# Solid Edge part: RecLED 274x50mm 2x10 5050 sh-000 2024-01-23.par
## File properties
Author: jaroslaw.przewlocki
Template: iso metric part.par
Last saved by: jaroslaw.przewlocki
Revision: 2
Application: Solid Edge
Gęstość: 0,000 kg/m^3
Dokładność: 0,990
Username: jaroslaw.przewlocki
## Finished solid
Body 1: solid body, 1056 faces, 2675 edges, 1702 vertices.
  Faces by surface: plane 523, cylinder 269, torus 104, cone 88, spline 51, sphere 20, swept 1
  Edges by curve: line 1410, curve on surface 677, circle 296, spline 160, ellipse 132
Bounding box of the edges (mm; curved faces can reach further): 49.500 x 4.950 x 273.800, from (-24.75, -3.45, -111.5) to (24.75, 1.5, 162.3).
Cylindrical faces by radius (mm): R0.199 x2, R0.2 x78, R0.2002 x4, R0.2169 x6, R0.25 x24, R0.3 x4, R0.3373 x6, R0.4 x16, R0.4006 x4, R0.4008 x4, R0.525 x4, R0.6 x24, R1 x14, R1.05 x20, R1.0894 x4, R1.0991 x8, R1.1 x28, R1.5342 x3, R1.5343 x1, R1.75 x5, R3.7549 x1, R5.3685 x1, R5.3987 x1, R5.4728 x1, R5.8982 x1, R7.5931 x1, R7.8648 x1, R8.5931 x1, R10.3711 x1, R11.964 x1
Conical faces (half-angle, radius in mm at the cone's reference point): 0.3913 deg R1.0968 x4, 0.447 deg R1.0952 x4, 0.464 deg R1.0955 x4, 0.5 deg R0.5056 x8, 0.5 deg R1.0082 x8, 1 deg R0.5511 x4, 10 deg R0.2132 x4, 10 deg R0.4132 x4, 15.6748 deg R1.1041 x2, 15.6751 deg R1.1041 x2, 15.7937 deg R1.1267 x2, 15.7938 deg R1.1267 x2, 18.4844 deg R1.0657 x8, 18.9316 deg R0.5099 x4, 19.4337 deg R0.5111 x4, 27.363 deg R0.6214 x4, 40.1968 deg R0.519 x2, 40.228 deg R0.5176 x2, 42.9179 deg R0.4919 x2, 42.9331 deg R0.4916 x2, 45 deg R0.575 x4, 45 deg R0.625 x8
Toroidal faces (ring radius, tube radius in mm): R0.0958 r0.3997 x8, R0.1 r0.2 x2, R0.1075 r0.4 x4, R0.1101 r0.4001 x4, R0.1216 r0.4 x4, R0.1234 r0.4 x4, R0.1634 r0.2287 x2, R0.1641 r0.2287 x2, R0.3286 r0.2001 x2, R0.3702 r0.4 x4, R0.3818 r0.2 x4, R0.4163 r0.3984 x4, R0.4824 r0.2001 x2, R0.4952 r0.2 x2, R0.6008 r0.3968 x4, R0.6009 r0.3969 x4, R0.6227 r0.2 x2, R0.6235 r0.2 x2, R0.8 r0.2 x8, R0.8522 r0.3 x4, R0.9002 r0.2 x2, R0.9018 r0.2 x2, R0.9181 r0.2227 x4, R0.9197 r0.223 x2, R0.9199 r0.223 x2, R0.9663 r0.2263 x2, R0.9665 r0.2263 x2, R1.3 r0.2 x4, R1.327 r1.1 x4, R1.3271 r1.1 x4, R1.8741 r0.2175 x2, R1.8987 r0.2 x2
Spherical faces by radius (mm): R0.2 x16, R0.6 x4
Planar faces by outward normal: +x 53, +y 15, +z 49, -x 53, -y 89, -z 68, oblique 196
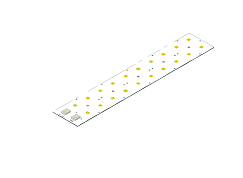
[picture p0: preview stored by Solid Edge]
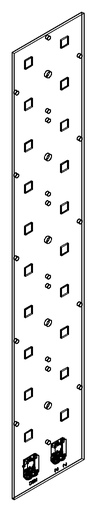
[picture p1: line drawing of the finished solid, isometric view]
